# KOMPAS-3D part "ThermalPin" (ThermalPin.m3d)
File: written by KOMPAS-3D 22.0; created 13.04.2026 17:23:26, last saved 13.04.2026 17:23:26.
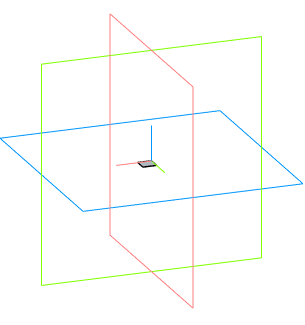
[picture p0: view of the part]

Document properties: Автор: Andrey; Полное имя файла: C:\Users\User1\Documents\ThermalPin.m3d

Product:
- Part/product: ThermalPin

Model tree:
1. Операция без истории:1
